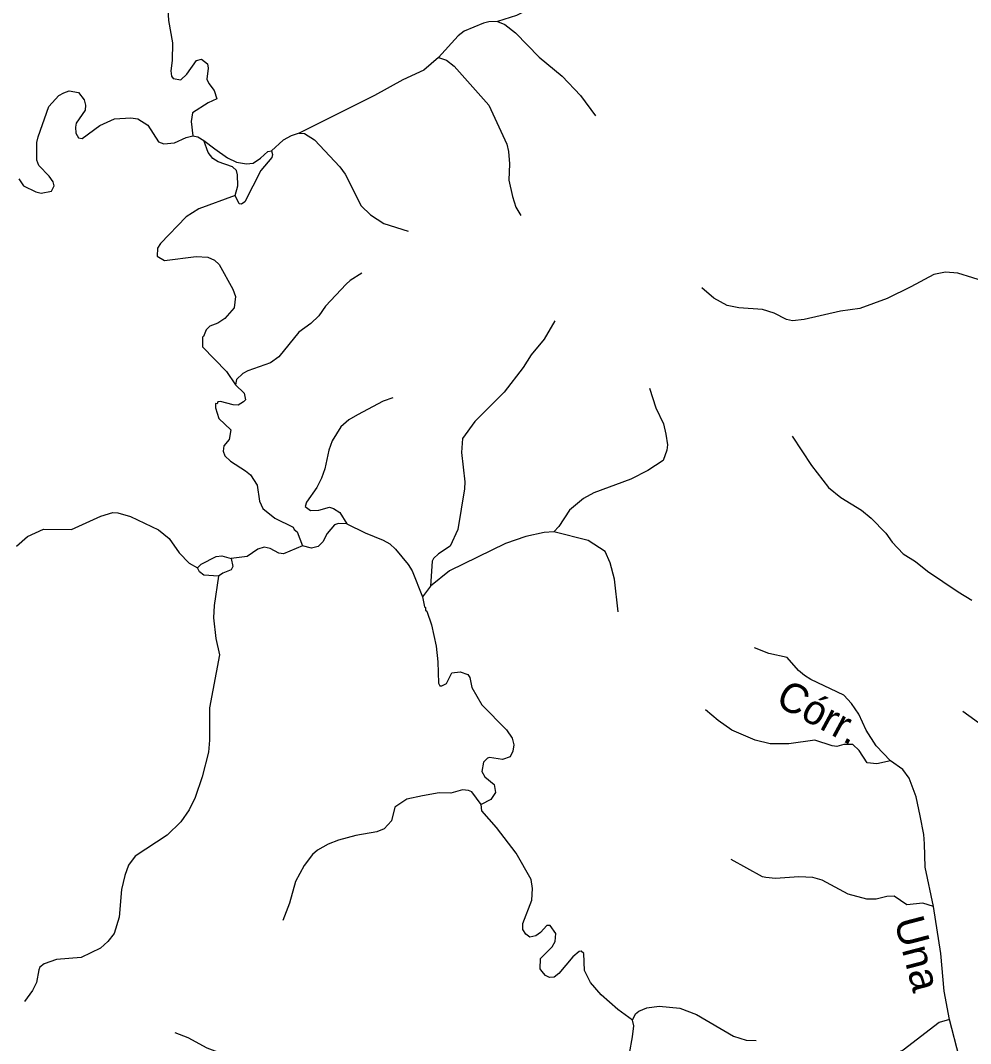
# Model space of a CAD drawing. Extents: x 346.5 to 372.4, y 7400.3 to 7428.2.
# Drawn here: x 359.493 to 362.074, y 7419.897 to 7422.676 of the extents above; entities that cross this region are included whole.
import ezdxf
from ezdxf.enums import TextEntityAlignment as Align

# ---------------------------------------------------------------- set-up
doc = ezdxf.new("R2010")
doc.units = 0
doc.header["$LTSCALE"] = 0.032
doc.layers.add('2', color=7, linetype='Continuous', lineweight=25)
doc.layers.add('7', color=7, linetype='Continuous', lineweight=25)
doc.layers.add('61', color=7, linetype='Continuous')

msp = doc.modelspace()

# ---------------------------------------------------------------- linework, layer by layer
at = {"layer": '2'}
for points in [[(359.9914, 7422.3501), (360.0209, 7422.3274), (360.0554, 7422.3029), (360.0798, 7422.2907), (360.1071, 7422.2864), (360.1251, 7422.2885), (360.1451, 7422.3018), (360.1656, 7422.3201), (360.1749, 7422.3214), (360.1777, 7422.3114), (360.176, 7422.3038), (360.1465, 7422.2684), (360.1025, 7422.1832), (360.0937, 7422.1769), (360.0875, 7422.1782), (360.0766, 7422.2007), (360.0839, 7422.2271), (360.0832, 7422.257), (360.08, 7422.268), (360.0692, 7422.2779), (360.0301, 7422.2919), (360.0162, 7422.3013), (360.0032, 7422.3168)], [(359.9746, 7421.1895), (359.9845, 7421.1994), (360.0251, 7421.2202), (360.0399, 7421.2217), (360.066, 7421.2141), (360.0705, 7421.1931), (360.0654, 7421.1834), (360.0434, 7421.1744), (360.0317, 7421.1661), (359.9918, 7421.1689), (359.9794, 7421.1785)]]:
    msp.add_lwpolyline(points, close=True, dxfattribs=at)
at = {"layer": '7'}
for points in [[(359.9133, 7422.7874), (359.9018, 7422.7538), (359.8938, 7422.7059), (359.8954, 7422.6756), (359.9066, 7422.6151), (359.9058, 7422.5673), (359.9018, 7422.5386), (359.9034, 7422.5242), (359.9082, 7422.5186), (359.9289, 7422.5146), (359.9456, 7422.5298), (359.9711, 7422.5672), (359.9847, 7422.5704), (359.9934, 7422.5648), (360.0014, 7422.5585), (360.003, 7422.5465), (359.9998, 7422.5163), (360.0046, 7422.5043), (360.0197, 7422.486), (360.0269, 7422.4629), (360.003, 7422.4517), (359.9608, 7422.4246), (359.9568, 7422.4015), (359.9615, 7422.3629)], [(360.8868, 7422.7267), (360.882, 7422.7155), (360.8565, 7422.6971), (360.8407, 7422.6892), (360.7887, 7422.6729)], [(360.7887, 7422.6729), (360.7657, 7422.6724), (360.7513, 7422.6685), (360.6987, 7422.6469), (360.682, 7422.6342), (360.629, 7422.5757)], [(360.7887, 7422.6729), (360.8087, 7422.6645), (360.8374, 7422.6422), (360.9019, 7422.576), (360.9649, 7422.5242), (361.0143, 7422.4724), (361.055, 7422.4166)], [(360.629, 7422.5757), (360.5888, 7422.5409), (360.5322, 7422.5146), (360.4549, 7422.4716), (360.2501, 7422.3698)], [(360.629, 7422.5757), (360.6501, 7422.568), (360.6716, 7422.5513), (360.7657, 7422.4461), (360.8143, 7422.3401), (360.8191, 7422.3202), (360.8215, 7422.2867), (360.8199, 7422.2421), (360.8294, 7422.1975), (360.839, 7422.1688), (360.8525, 7422.1457)], [(359.489, 7422.2453), (359.5017, 7422.227), (359.5352, 7422.2102), (359.5495, 7422.207), (359.5774, 7422.2126), (359.5846, 7422.2269), (359.5822, 7422.2373), (359.5718, 7422.2533), (359.5432, 7422.282), (359.5376, 7422.2963), (359.5384, 7422.3441), (359.5416, 7422.3601), (359.5702, 7422.4421), (359.5974, 7422.4724), (359.6117, 7422.4796), (359.6261, 7422.4844), (359.6515, 7422.4804), (359.6667, 7422.4605), (359.6699, 7422.4461), (359.6691, 7422.4318), (359.6452, 7422.3967), (359.6428, 7422.3856), (359.6436, 7422.3696), (359.6507, 7422.3569), (359.6611, 7422.3553), (359.7089, 7422.3903), (359.7488, 7422.4087), (359.7934, 7422.4118), (359.8125, 7422.4087), (359.8396, 7422.3911), (359.8683, 7422.3465), (359.8827, 7422.3409), (359.9114, 7422.3433), (359.9439, 7422.3584), (359.9615, 7422.3629)], [(359.9615, 7422.3629), (359.9748, 7422.3597), (359.9914, 7422.3501)], [(360.2501, 7422.3698), (360.2285, 7422.3624), (360.207, 7422.3505), (360.1749, 7422.3214)], [(360.2501, 7422.3698), (360.2645, 7422.3689), (360.2923, 7422.352), (360.3608, 7422.278), (360.3752, 7422.2581), (360.419, 7422.172), (360.4445, 7422.1481), (360.4804, 7422.1241), (360.5465, 7422.1034)], [(360.0766, 7422.2007), (359.9775, 7422.164), (359.9432, 7422.1425), (359.8739, 7422.07), (359.8659, 7422.0572), (359.8651, 7422.0357), (359.885, 7422.0237), (359.9703, 7422.0349), (360.0022, 7422.0333), (360.0205, 7422.0245), (360.0333, 7422.0126), (360.0699, 7421.9456), (360.0771, 7421.9257), (360.0739, 7421.8954), (360.0484, 7421.8667), (360.0293, 7421.854), (360.0078, 7421.8452), (359.9982, 7421.8356), (359.991, 7421.8173), (359.9878, 7421.8157), (359.9878, 7421.7894), (360.0532, 7421.7225), (360.0777, 7421.6864)], [(360.4206, 7421.9895), (360.3887, 7421.9695), (360.3776, 7421.9592), (360.3218, 7421.9002), (360.3034, 7421.8739), (360.2819, 7421.8524), (360.2493, 7421.8293), (360.1951, 7421.7623), (360.1728, 7421.7456), (360.1106, 7421.7241), (360.0978, 7421.7169), (360.0801, 7421.7011), (360.0777, 7421.6864)], [(362.1204, 7421.9644), (362.0392, 7421.9895), (362.0057, 7421.9926), (361.9739, 7421.9863), (361.9117, 7421.9528), (361.8471, 7421.9209), (361.773, 7421.8938), (361.7204, 7421.8859), (361.6216, 7421.8635), (361.5897, 7421.8596), (361.5738, 7421.8635), (361.5403, 7421.8811), (361.5084, 7421.8906), (361.4447, 7421.8954), (361.4128, 7421.9018), (361.3761, 7421.9217), (361.3435, 7421.9496)], [(360.945, 7421.8604), (360.9155, 7421.8102), (360.8804, 7421.7679), (360.8589, 7421.7329), (360.8071, 7421.6667), (360.7274, 7421.587), (360.6939, 7421.5408), (360.6908, 7421.5025), (360.7003, 7421.4229), (360.6995, 7421.4037), (360.6812, 7421.2929), (360.6605, 7421.2483), (360.6286, 7421.2276), (360.6151, 7421.2148), (360.6111, 7421.2069), (360.6068, 7421.1396)], [(360.0777, 7421.6864), (360.101, 7421.6635), (360.1042, 7421.6452), (360.0994, 7421.6396), (360.0851, 7421.6308), (360.0707, 7421.6316), (360.0365, 7421.6412), (360.0293, 7421.6396), (360.0277, 7421.6348), (360.0229, 7421.6356), (360.0229, 7421.6237), (360.0325, 7421.595), (360.0644, 7421.5639), (360.0604, 7421.5376), (360.046, 7421.5209), (360.0436, 7421.5057), (360.0484, 7421.4938), (360.0643, 7421.4786), (360.105, 7421.4523), (360.1178, 7421.442), (360.1361, 7421.4133), (360.1425, 7421.3703), (360.152, 7421.3503), (360.1847, 7421.324), (360.2341, 7421.2993), (360.2365, 7421.2929), (360.2445, 7421.2866), (360.2598, 7421.249)], [(361.2016, 7421.6771), (361.2191, 7421.6237), (361.2399, 7421.5806), (361.2462, 7421.552), (361.2502, 7421.5233), (361.2486, 7421.5089), (361.2391, 7421.481), (361.1976, 7421.4539), (361.1514, 7421.43), (361.051, 7421.3933), (361.0223, 7421.3774), (360.9848, 7421.3455), (360.9552, 7421.3011), (360.9417, 7421.2871)], [(360.5051, 7421.6508), (360.4788, 7421.642), (360.4087, 7421.6045), (360.3855, 7421.591), (360.3632, 7421.5719), (360.3401, 7421.5344), (360.3305, 7421.5089), (360.3202, 7421.4579), (360.3114, 7421.4324), (360.2987, 7421.4069), (360.27, 7421.3679), (360.2668, 7421.3559), (360.2811, 7421.3447), (360.3035, 7421.3455), (360.3329, 7421.3543), (360.3433, 7421.3503), (360.3608, 7421.3392), (360.3796, 7421.309)], [(361.5889, 7421.5464), (361.6415, 7421.4675), (361.6877, 7421.4069), (361.7212, 7421.3798), (361.7778, 7421.3455), (361.8041, 7421.324), (361.8439, 7421.2834), (361.8607, 7421.2587), (361.8902, 7421.2268), (361.9244, 7421.2061), (361.9571, 7421.1798), (362.04, 7421.124), (362.0775, 7421.1017)], [(359.4829, 7421.2481), (359.5129, 7421.2738), (359.5559, 7421.2945), (359.6324, 7421.2929), (359.7121, 7421.3296), (359.744, 7421.3392), (359.7583, 7421.3384), (359.7926, 7421.3288), (359.8683, 7421.2921), (359.897, 7421.269), (359.9249, 7421.23), (359.9516, 7421.2017), (359.9746, 7421.1895)], [(360.3796, 7421.309), (360.3571, 7421.3095), (360.3465, 7421.3057), (360.3265, 7421.2826), (360.3146, 7421.2595), (360.3019, 7421.2467), (360.2835, 7421.2427), (360.2598, 7421.249)], [(360.3796, 7421.309), (360.4294, 7421.2842), (360.4788, 7421.2642), (360.4963, 7421.2539), (360.5122, 7421.2395), (360.5465, 7421.1981), (360.5569, 7421.1806), (360.5854, 7421.1101)], [(360.9417, 7421.2871), (360.9155, 7421.285), (360.8661, 7421.2746), (360.8103, 7421.2555), (360.6589, 7421.1806), (360.6068, 7421.1396), (360.5854, 7421.1101)], [(361.1163, 7421.0698), (361.1068, 7421.1583), (361.0948, 7421.2029), (361.0813, 7421.2332), (361.0351, 7421.2634), (360.9417, 7421.2871)], [(360.2598, 7421.249), (360.2078, 7421.2276), (360.1951, 7421.2292), (360.1712, 7421.2419), (360.1552, 7421.2451), (360.1385, 7421.2395), (360.1087, 7421.2203), (360.066, 7421.2141)], [(360.0317, 7421.1661), (360.0197, 7421.0865), (360.0181, 7421.0531), (360.0237, 7420.9973), (360.0341, 7420.9527), (360.007, 7420.8092), (360.007, 7420.7215), (360.0038, 7420.6881), (359.9871, 7420.6211), (359.9679, 7420.5653), (359.9512, 7420.5319), (359.9289, 7420.4992), (359.8922, 7420.4633), (359.8054, 7420.4059), (359.787, 7420.382), (359.7767, 7420.3533), (359.7679, 7420.3151), (359.7615, 7420.2402), (359.748, 7420.1956), (359.7312, 7420.174), (359.7105, 7420.1565), (359.6579, 7420.131), (359.591, 7420.1254), (359.5575, 7420.1135), (359.5463, 7420.1047), (359.5432, 7420.0975), (359.5368, 7420.0633), (359.5264, 7420.0409), (359.5041, 7420.0115)], [(360.5854, 7421.1101), (360.5903, 7421.0834), (360.5935, 7421.081), (360.5935, 7421.0738), (360.5967, 7421.0714), (360.6095, 7421.0339), (360.6222, 7420.9766), (360.627, 7420.9335), (360.6286, 7420.8761), (360.6326, 7420.869), (360.6382, 7420.8682), (360.6501, 7420.8753), (360.6653, 7420.904), (360.6876, 7420.9064), (360.7083, 7420.8992), (360.7139, 7420.8913), (360.7194, 7420.8642), (360.7465, 7420.8172), (360.8135, 7420.7494), (360.8286, 7420.7263), (360.8334, 7420.7088), (360.831, 7420.6913), (360.823, 7420.6761), (360.8023, 7420.6689), (360.7673, 7420.6737), (360.7617, 7420.6721), (360.7505, 7420.6609), (360.7465, 7420.6362), (360.7545, 7420.6219), (360.78, 7420.6004), (360.7832, 7420.5789), (360.7704, 7420.5597), (360.7446, 7420.5463)], [(361.8564, 7420.6652), (361.8176, 7420.7056), (361.7905, 7420.7486), (361.7698, 7420.7917), (361.7507, 7420.8204), (361.7292, 7420.8435), (361.6399, 7420.8857), (361.6224, 7420.8968), (361.6064, 7420.9104), (361.5753, 7420.9455), (361.526, 7420.9566), (361.4869, 7420.9718)], [(361.8564, 7420.6652), (361.8192, 7420.657), (361.7929, 7420.6594), (361.7714, 7420.6928), (361.7539, 7420.7096), (361.7292, 7420.7096), (361.7109, 7420.704), (361.6981, 7420.7056), (361.6511, 7420.7215), (361.5802, 7420.7112), (361.5292, 7420.7112), (361.4885, 7420.7215), (361.4256, 7420.7486), (361.3881, 7420.7741), (361.3538, 7420.8036)], [(362.0527, 7420.7996), (362.1117, 7420.7574), (362.1141, 7420.7526), (362.1229, 7420.751), (362.1237, 7420.7478), (362.1388, 7420.7383), (362.1787, 7420.7167), (362.2337, 7420.6681), (362.3317, 7420.5924), (362.3883, 7420.5581), (362.419, 7420.5441)], [(361.9734, 7420.2694), (361.9499, 7420.3757), (361.9483, 7420.4394), (361.9467, 7420.4649), (361.9372, 7420.5159), (361.926, 7420.5669), (361.9069, 7420.6179), (361.8894, 7420.6418), (361.8564, 7420.6652)], [(360.7446, 7420.5463), (360.7195, 7420.5805), (360.7099, 7420.5844), (360.694, 7420.586), (360.6621, 7420.5773), (360.6302, 7420.5781), (360.5856, 7420.5701), (360.5425, 7420.5605), (360.5098, 7420.539), (360.5011, 7420.5024), (360.4812, 7420.48), (360.4612, 7420.4721), (360.4039, 7420.4625), (360.3576, 7420.4498), (360.329, 7420.4386), (360.3003, 7420.4227), (360.2867, 7420.4107), (360.2636, 7420.3804), (360.2405, 7420.3374), (360.2237, 7420.2784), (360.2062, 7420.2314)], [(361.1553, 7419.9603), (361.1161, 7419.9893), (361.0701, 7420.029), (361.0414, 7420.0633), (361.0255, 7420.0951), (361.0231, 7420.1413), (361.0159, 7420.1477), (361.0111, 7420.1469), (360.9936, 7420.1326), (360.9553, 7420.0872), (360.9426, 7420.0776), (360.9298, 7420.0762), (360.9195, 7420.0816), (360.9091, 7420.0935), (360.9051, 7420.0999), (360.9059, 7420.1278), (360.9378, 7420.1597), (360.9458, 7420.174), (360.9474, 7420.1956), (360.9322, 7420.2178), (360.9227, 7420.2178), (360.9059, 7420.1987), (360.8932, 7420.1892), (360.8772, 7420.186), (360.8661, 7420.1939), (360.8581, 7420.2067), (360.8581, 7420.2227), (360.882, 7420.2864), (360.8836, 7420.3183), (360.8804, 7420.343), (360.8398, 7420.4139), (360.7864, 7420.484), (360.7466, 7420.5287), (360.7446, 7420.5463)], [(361.9734, 7420.2694), (361.9444, 7420.2784), (361.9005, 7420.2736), (361.8663, 7420.2975), (361.8463, 7420.2968), (361.8177, 7420.2888), (361.7921, 7420.2888), (361.7411, 7420.3031), (361.671, 7420.3406), (361.6455, 7420.3478), (361.6073, 7420.3501), (361.5435, 7420.3454), (361.518, 7420.3478), (361.5084, 7420.3501), (361.4232, 7420.3972)], [(362.0166, 7419.962), (362.0017, 7420.0394), (361.993, 7420.1414), (361.9734, 7420.2694)], [(361.1553, 7419.9603), (361.1641, 7419.978), (361.1729, 7419.9851), (361.1944, 7419.9939), (361.2279, 7419.9987), (361.2837, 7419.9931), (361.3291, 7419.9764), (361.4295, 7419.9174), (361.4638, 7419.9062), (361.4917, 7419.9055)], [(361.167, 7419.808), (361.1522, 7419.8441), (361.1498, 7419.8449), (361.1474, 7419.8704), (361.1554, 7419.915), (361.1594, 7419.9453), (361.1553, 7419.9603)], [(362.0166, 7419.962), (361.9882, 7419.9541), (361.8902, 7419.8792), (361.7714, 7419.825), (361.7244, 7419.7947)], [(362.0681, 7419.8303), (362.0479, 7419.8505), (362.0424, 7419.8608), (362.0166, 7419.962)], [(360.2543, 7419.7076), (360.2481, 7419.7337), (360.2397, 7419.7517), (360.2357, 7419.754), (360.215, 7419.7987), (360.1847, 7419.8353), (360.1695, 7419.8465), (360.1425, 7419.8552), (360.0787, 7419.8568), (360.066, 7419.86), (360.0006, 7419.8847), (359.9488, 7419.9126), (359.9137, 7419.9262)]]:
    msp.add_lwpolyline(points, dxfattribs=at)

# ---------------------------------------------------------------- texts
at = {"layer": '61'}
msp.add_text('Córr.', height=0.08, rotation=331.695, dxfattribs=at).set_placement((361.6448, 7420.7621), align=Align.CENTER)
at = {"layer": '61', "width": 1.05}
msp.add_text('Una', height=0.08, rotation=284.677, dxfattribs=at).set_placement((361.8922, 7420.1317), align=Align.CENTER)

doc.saveas('drawing.dxf')
